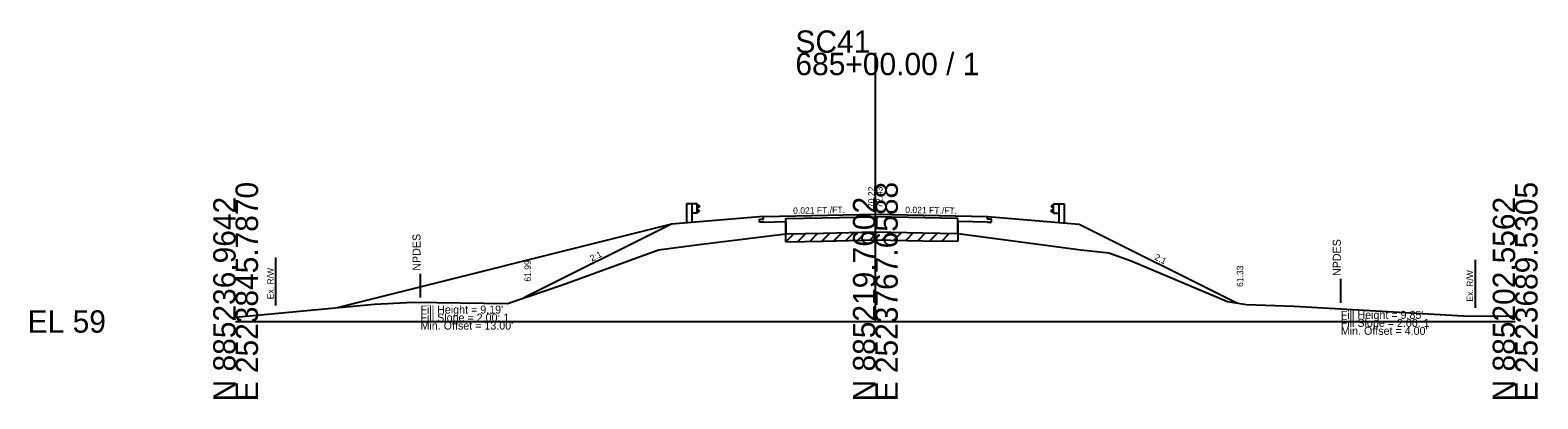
# Model space of a CAD drawing. Extents: x -26 to 183, y -10 to 24021.
# Drawn here: x -25.7 to 162.8, y 14490.3 to 14536.5 of the extents above; entities that cross this region are included whole.
import ezdxf

# ---------------------------------------------------------------- set-up
doc = ezdxf.new("R2010")
doc.units = 0
for name, color, linetype in [('RD_GPK_XS_Cell', 7, 'Continuous'), ('RD_XS_Base', 7, 'Continuous'), ('RD_XS_Buildup', 7, 'Continuous'), ('RD_XS_EarthShd', 7, 'Continuous'), ('RD_XS_ExGround', 7, 'Continuous'), ('RD_XS_ExPaveRet', 7, 'Continuous'), ('RD_XS_ExRW', 7, 'Continuous'), ('RD_XS_GR', 7, 'Continuous'), ('RD_XS_NPDES', 7, 'Continuous'), ('RD_XS_Pave', 7, 'Continuous'), ('RD_XS_TieSlope', 7, 'Continuous'), ('RD_XS_TX_Elev_EX', 7, 'Continuous'), ('RD_XS_TX_Elev_PR', 7, 'Continuous'), ('RD_XS_TX_Slope', 7, 'Continuous'), ('RD_XS_TX_Warning', 7, 'Continuous')]:
    doc.layers.add(name, color=color, linetype=linetype)

msp = doc.modelspace()

# ---------------------------------------------------------------- linework, layer by layer
at = {"layer": 'RD_GPK_XS_Cell'}
for p, q in [((80, 14500), (80, 14533.65)), ((0, 14500), (80, 14500)), ((80, 14500), (160, 14500))]:
    msp.add_line(p, q, dxfattribs=at)
at = {"layer": 'RD_XS_Base'}
for p, q in [((66, 14512.46), (68.8, 14512.52)), ((68.8, 14512.52), (68.8, 14510.97)), ((90.33, 14512.53), (90.33, 14511.04)), ((94, 14512.46), (90.33, 14512.53))]:
    msp.add_line(p, q, dxfattribs=at)
at = {"layer": 'RD_XS_Buildup'}
for p, q in [((68.8, 14512.88), (80, 14513.11)), ((68.8, 14510.97), (68.8, 14512.88)), ((90.33, 14512.89), (80, 14513.11)), ((90.33, 14511.04), (90.33, 14512.89))]:
    msp.add_line(p, q, dxfattribs=at)
at = {"layer": 'RD_XS_EarthShd'}
for p, q in [((58, 14512.47), (54.5, 14512.18)), ((66, 14513.14), (58, 14512.47)), ((94, 14513.14), (102, 14512.47)), ((102, 14512.47), (105.5, 14512.18))]:
    msp.add_line(p, q, dxfattribs=at)
at = {"layer": 'RD_XS_ExGround'}
for p, q in [((52.88, 14508.97), (57.95, 14509.64)), ((57.95, 14509.64), (68.8, 14510.97)), ((68.8, 14510.97), (73.53, 14511.06)), ((73.53, 14511.06), (79.94, 14511.22)), ((79.94, 14511.22), (85.94, 14511.1)), ((85.94, 14511.1), (90.33, 14511.04)), ((90.33, 14511.04), (105.69, 14508.98)), ((40.87, 14504.6), (52.88, 14508.97)), ((105.69, 14508.98), (109.21, 14508.6)), ((109.21, 14508.6), (112, 14507.59)), ((112, 14507.59), (124.05, 14502.51)), ((33.98, 14502.26), (40.87, 14504.6)), ((0, 14500.53), (17.36, 14502.17)), ((17.36, 14502.17), (22.19, 14502.42)), ((22.19, 14502.42), (33.98, 14502.26)), ((124.05, 14502.51), (126.41, 14502.14)), ((126.41, 14502.14), (132.36, 14501.94)), ((132.36, 14501.94), (153.56, 14500.73)), ((153.56, 14500.73), (160, 14500.67))]:
    msp.add_line(p, q, dxfattribs=at)
at = {"layer": 'RD_XS_ExPaveRet'}
for p, q in [((68.8, 14509.97), (69.82, 14510.99)), ((68.8, 14509.97), (68.8, 14510.97)), ((68.8, 14509.97), (73.53, 14510.06)), ((70.3, 14510), (71.32, 14511.02)), ((71.8, 14510.03), (72.82, 14511.05)), ((73.3, 14510.06), (74.32, 14511.08)), ((73.53, 14510.06), (79.94, 14510.22)), ((74.8, 14510.09), (75.82, 14511.12)), ((76.3, 14510.13), (77.32, 14511.15)), ((77.8, 14510.17), (78.82, 14511.19)), ((79.3, 14510.2), (80.31, 14511.21)), ((79.94, 14510.22), (85.94, 14510.1)), ((80.8, 14510.2), (81.78, 14511.18)), ((82.3, 14510.17), (83.28, 14511.15)), ((83.8, 14510.14), (84.78, 14511.13)), ((85.3, 14510.12), (86.28, 14511.1)), ((85.94, 14510.1), (90.33, 14510.04)), ((86.8, 14510.09), (87.78, 14511.08)), ((88.3, 14510.07), (89.28, 14511.05)), ((90.33, 14511.04), (90.33, 14510.04))]:
    msp.add_line(p, q, dxfattribs=at)
at = {"layer": 'RD_XS_ExRW'}
for p, q in [((5, 14508), (5, 14502)), ((155, 14507.72), (155, 14501.72))]:
    msp.add_line(p, q, dxfattribs=at)
at = {"layer": 'RD_XS_GR'}
for p, q in [((56.4, 14514.72), (56.4, 14512.34)), ((57.06, 14514.72), (56.4, 14514.72)), ((57.06, 14514.72), (57.06, 14512.39)), ((57.73, 14514.72), (57.06, 14514.72)), ((57.73, 14513.55), (57.06, 14513.55)), ((57.73, 14513.55), (57.73, 14514.72)), ((57.73, 14514.65), (58, 14514.45)), ((58, 14514.4), (57.73, 14514.2)), ((58, 14513.88), (57.73, 14514.08)), ((57.73, 14513.63), (58, 14513.83)), ((58, 14514.45), (58, 14514.4)), ((58, 14513.83), (58, 14513.88)), ((102.27, 14514.65), (102, 14514.45)), ((102, 14514.45), (102, 14514.4)), ((102, 14514.4), (102.27, 14514.2)), ((102, 14513.88), (102.27, 14514.08)), ((102, 14513.83), (102, 14513.88)), ((102.27, 14513.63), (102, 14513.83)), ((102.27, 14513.55), (102.27, 14514.72)), ((102.27, 14514.72), (102.94, 14514.72)), ((102.27, 14513.55), (102.94, 14513.55)), ((102.94, 14514.72), (102.94, 14512.39)), ((102.94, 14514.72), (103.6, 14514.72)), ((103.6, 14514.72), (103.6, 14512.34))]:
    msp.add_line(p, q, dxfattribs=at)
at = {"layer": 'RD_XS_NPDES'}
for p, q in [((23.12, 14502.99), (23.12, 14505.99)), ((138.2, 14502.33), (138.2, 14505.33))]:
    msp.add_line(p, q, dxfattribs=at)
at = {"layer": 'RD_XS_Pave'}
for p, q in [((66, 14513.14), (80, 14513.43)), ((80, 14513.43), (94, 14513.14)), ((54.5, 14512.18), (12.71, 14501.73)), ((65.5, 14512.81), (66, 14512.82)), ((65.5, 14512.45), (65.5, 14512.81)), ((66, 14512.46), (65.5, 14512.45)), ((66, 14512.82), (66, 14513.14)), ((94, 14512.82), (94, 14513.14)), ((94.5, 14512.81), (94, 14512.82)), ((94, 14512.46), (94.5, 14512.45)), ((94.5, 14512.45), (94.5, 14512.81))]:
    msp.add_line(p, q, dxfattribs=at)
at = {"layer": 'RD_XS_TieSlope'}
for p, q in [((54.5, 14512.18), (36.12, 14502.99)), ((105.5, 14512.18), (125.2, 14502.33))]:
    msp.add_line(p, q, dxfattribs=at)

# ---------------------------------------------------------------- texts
at = {"layer": 'RD_GPK_XS_Cell'}
for s, p in [('SC41', (70, 14533.65)), ('685+00.00 / 1', (70, 14530.85)), ('EL 59', (-26, 14498.6))]:
    msp.add_text(s, height=2.8, dxfattribs=at).set_placement(p)
for s, p in [('E 2523845.7870', (2.8, 14490)), ('E 2523767.6588', (82.8, 14490)), ('E 2523689.5305', (162.8, 14490)), ('N 885236.9642', (0, 14490)), ('N 885219.7602', (80, 14490)), ('N 885202.5562', (160, 14490))]:
    msp.add_text(s, height=2.8, rotation=90, dxfattribs=at).set_placement(p)
at = {"layer": 'RD_XS_ExRW'}
for p in [(4.75, 14502.79), (154.75, 14502.5)]:
    msp.add_text('Ex. R/W ', height=0.8, rotation=90, dxfattribs=at).set_placement(p)
at = {"layer": 'RD_XS_TX_Elev_EX'}
msp.add_text('70.22', height=0.8, rotation=90, dxfattribs=at).set_placement((79.9, 14514.22))
at = {"layer": 'RD_XS_TX_Elev_PR'}
for s, p in [('72.43', (80.9, 14514.22)), ('61.99', (36.92, 14504.99)), ('61.33', (126, 14504.33))]:
    msp.add_text(s, height=0.8, rotation=90, dxfattribs=at).set_placement(p)
at = {"layer": 'RD_XS_TX_Slope'}
for s, rotation, p in [('0.021 FT./FT.', 1.1916, (69.72, 14513.47)), ('0.021 FT./FT.', 358.8084, (83.73, 14513.6)), ('2:1', 26.5651, (44.56, 14507.49)), ('2:1', 333.4349, (114.82, 14507.8))]:
    msp.add_text(s, height=0.8, rotation=rotation, dxfattribs=at).set_placement(p)
at = {"layer": 'RD_XS_TX_Warning'}
for p in [(23.12, 14505.99), (138.2, 14505.33)]:
    msp.add_text(' NPDES', height=1, rotation=90, dxfattribs=at).set_placement(p)
for s, p in [("Fill Height = 9.19' ", (23.12, 14500.99)), ('Fill Slope = 2.00: 1', (23.12, 14499.99)), ("Min. Offset = 13.00' ", (23.12, 14498.99)), ("Fill Height = 9.85' ", (138.2, 14500.33)), ('Fill Slope = 2.00: 1', (138.2, 14499.33)), ("Min. Offset = 4.00' ", (138.2, 14498.33))]:
    msp.add_text(s, height=1, dxfattribs=at).set_placement(p)

doc.saveas('drawing.dxf')
